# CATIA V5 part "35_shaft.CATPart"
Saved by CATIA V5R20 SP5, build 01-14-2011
Part number: 35_shaft
Bounding box of the stored display mesh (mm): x -8.498 to 8.498, y 24.89 to 41.834, z -174.5 to -41.294
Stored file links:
  C:\Documents and Settings\anizard\Bureau\13\35_shaft.CATPart
  C:\Documents and Settings\anizard\Bureau\13\anizard.CATProduct
  C:\Program Files (x86)\Dassault Systemes\B20\intel_a\reffiles\standard\MetricThickPitch.txt
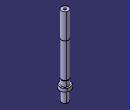
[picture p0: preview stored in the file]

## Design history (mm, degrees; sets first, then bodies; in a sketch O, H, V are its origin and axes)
Set1
  Plane1: linked copy from another document
  Line1: linked copy from another document
  Point1: linked copy from another document
  Plane2 to Plane7: linked copy from another document
  Point2 to Point4: linked copy from another document
Body1 (main body)
  Sketch1 on Plane1, origin (0, 0, 0), H (0, 1, 0), V (0, 0, 1)
    line L1 (33.3619, -174.5) -> (38.3619, -174.5)
    line L2 (38.3619, -174.5) -> (38.3619, -155.5)
    line L3 (38.3619, -155.5) -> (41.8619, -155.5)
    line L4 (41.8619, -155.5) -> (41.8619, -150.1)
    line L5 (41.8619, -150.1) -> (39.3619, -150.1)
    line L6 (39.3619, -150.1) -> (39.3619, -141.1)
    point P7 (39.3619, -141.1)
    line L7 (39.3619, -141.1) -> (39.0084, -140.7464)
    line L8 (39.0084, -140.7464) -> (39.0084, -83.6474)
    line L9 (39.0084, -83.6474) -> (39.3619, -83.2938)
    point P10 (39.3619, -83.2938)
    line L10 (39.3619, -83.2938) -> (39.3619, -41.2938)
    point P11 (39.3619, -41.2938)
    point P12 (39.3619, -41.2938)
    line L11 (39.3619, -41.2938) -> (33.3619, -41.2938)
    line L12 (33.3619, -41.2938) -> (33.3619, -174.5)
    reference projected line E1 (33.3619, -26) -> (33.3619, -181) from Line1
    reference projected point E2 (39.3619, -70.2938) from Point1
    reference intersected line E3 through (0, -40.2938) direction (1, 0) from Plane3
    reference intersected line E4 through (0, -82.2938) direction (1, 0) from Plane2
    reference intersected line E5 through (0, -155.5) direction (1, 0) from Plane4
    reference intersected line E6 through (0, -174.5) direction (-1, 0) from Plane5
    reference intersected line E7 through (0, -150.1) direction (1, 0) from Plane6
    reference intersected line E8 through (0, -142.1) direction (1, 0) from Plane7
    reference projected point E9 (38.3619, -155.5) from Point2
    angle L8 L9 = 45
    angle L7 L8 = 45
    distance L12 L4 = 8.5
    length L9 = 0.5
    distance E3 L11 = 1
    distance E4 P10 = 1
    distance P7 E8 = 1
    horizontal: L1 H, L3 H, L5 H, L11 H
    vertical: L2 V, L4 V, L6 V, L8 V, L10 V, L12 V
    coincidence: L12 E1, L10 L6, L10 E2, P11 P12, L3 E5, L1 E6, L5 E7, L2 E9
  Shaft1: profile Sketch1, axis Line1, angle 360
  Sketch2 on face of Shaft1 from Sketch1.L1, origin (0, 32, -174.5), H (1, 0, 0), V (0, -1, 0)
    point P1 (0, -1.3619)
    reference projected point E1 (0, -1.3619) from Point3
    coincidence: P1 E1
  Hole1: placed by Sketch2, at (0, 33.3619, -174.5) direction (0, 0, 1), diameter 4.134, depth 20, threaded "M5", thread diameter 5, thread depth 17, pitch 0.8
  Sketch3 on face of Shaft1 from Sketch1.L11, origin (0, 32, -41.2938), H (1, 0, 0), V (0, 1, 0)
    point P1 (0, 1.3619)
    reference projected point E1 (0, 1.3619) from Point4
    coincidence: P1 E1
  Hole2: placed by Sketch3, at (0, 33.3619, -41.2938) direction (0, 0, -1), diameter 4.134, depth 20, threaded "M5", thread diameter 5, thread depth 17, pitch 0.8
